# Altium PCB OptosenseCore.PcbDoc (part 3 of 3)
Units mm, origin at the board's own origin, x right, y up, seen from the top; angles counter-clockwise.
Board outline 65 x 56 mm, 4 copper layers (Top, Signal Layer 1, Power Layer 2, Bottom), stack 0.844 mm thick; 184 components, 119 nets, 728 pads, 633 vias.
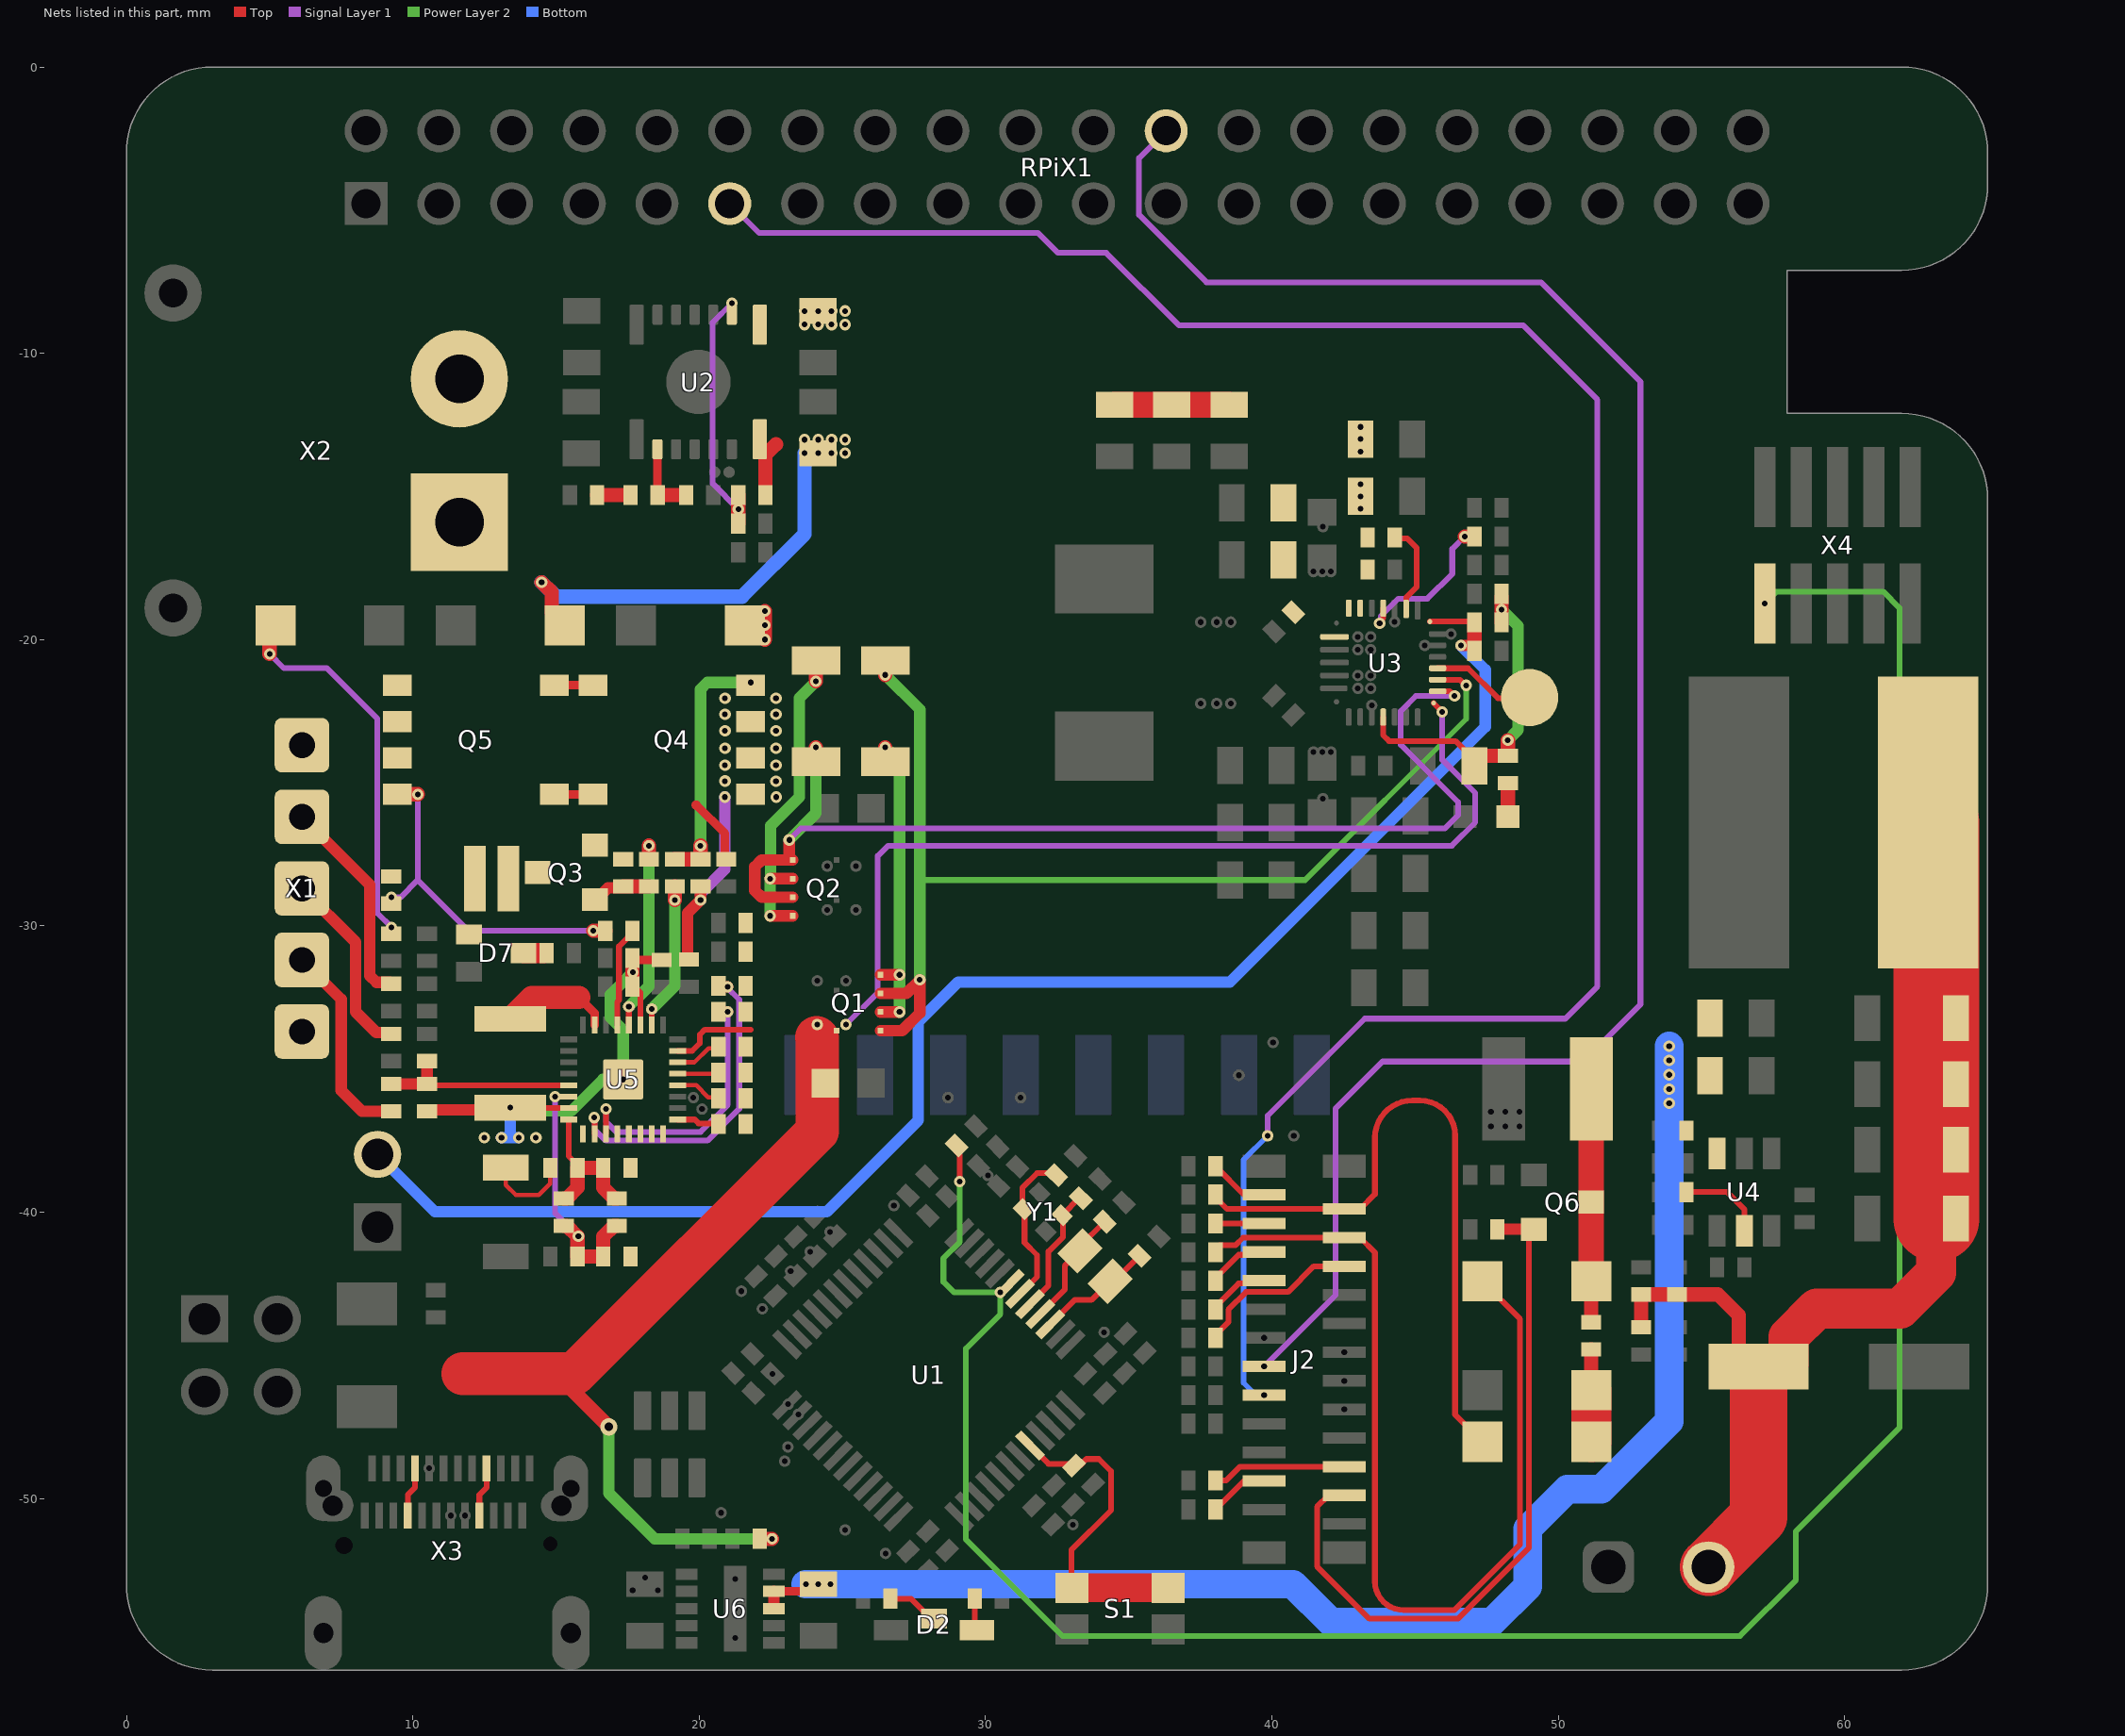
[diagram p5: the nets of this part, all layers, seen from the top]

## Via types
v1: diameter 0.4, hole 0.2, Top to Bottom, tented both sides, 616 vias
v2: diameter 0.5, hole 0.2, Top to Bottom, tented bottom, 11 vias
v3: diameter 4, hole 2.75, Top to Bottom, 4 vias
v4: diameter 0.4, hole 0.2, Top to Bottom, tented bottom, 1 vias
v5: diameter 0.6, hole 0.3, Top to Bottom, tented bottom, 1 vias

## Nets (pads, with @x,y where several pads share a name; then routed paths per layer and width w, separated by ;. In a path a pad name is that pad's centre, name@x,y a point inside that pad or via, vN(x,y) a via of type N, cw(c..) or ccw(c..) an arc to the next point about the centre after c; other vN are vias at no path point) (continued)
NetC62_1: C62.1 C64.2 R46.2 U5.5 | length 7
  Top w0.2: C64.2@10.5,-35.525 10.541,-35.566 U5.5@15.446,-35.566
  Top w0.4: R46.2@9.25,-35.525 C64.2@10.5,-35.525 C62.1@10.5,-34.725
NetC66_2: C66.2 U5.31 | length 3.9
  Top w0.3: 15.8,-32.5 16.346,-33.046 U5.31@16.346,-33.466
  Top w0.8: C66.2@13.4,-33.25 14.15,-32.5 15.8,-32.5
NetC67_1: C67.1 C68.2 C69.1 R53.2 U5.8 | length 5.4
  Top w0.2: U5.8@15.446,-36.766 15.446,-38.046 15.75,-38.35 R53.2@15.75,-38.45
  Top w0.5: C69.1@15.275,-39.525 15.375,-39.525 15.75,-39.15 R53.2@15.75,-38.45 C68.2@16.65,-38.45 16.65,-39.15 17.025,-39.525 C67.1@17.125,-39.525
NetC67_2: C67.2 C69.2 C70.1 R54.2 U5.6 | length 9.3
  Top w0.2: v1(14.966,-35.966) U5.6@15.446,-35.966
  Top w0.5: C69.2@15.275,-40.475 15.375,-40.475 15.75,-40.85 R54.2@15.75,-41.55 C70.1@16.65,-41.55 16.65,-40.85 17.025,-40.475 C67.2@17.125,-40.475
  Signal Layer 1 w0.2: v1(14.966,-35.966) 14.966,-40.027 v1(15.784,-40.845)
NetC71_1: C71.1 D11.A L3.2 Q6.C | length 8.3
  Top w0.5: C71.1@51.153,-43.847 D11.A@51.153,-42.422
  Top w0.9: D11.A@51.153,-42.422 L3.2@51.153,-35.5
NetC71_2: C71.2 D10.C D12.A | length 3.9
  Top w0.2: D12.A@50.675,-46.5 D12.A@51.153,-46.022
  Top w0.5: D12.A@51.153,-46.222 C71.2@51.153,-44.797
  Top w1.4: D10.C@51.153,-48.022 D12.A@51.153,-46.222
NetD2_1: D2.1 R12.2 | length 1.8
  Top w0.2: R12.2@26.675,-53.5 27.4,-53.5 28.1,-54.2 D2.1@28.2,-54.2
NetD2_3: D2.3 R13.2 | length 1.1
  Top w0.2: R13.2@29.625,-53.5 29.625,-54.525 D2.3@29.7,-54.6
NetD3_1: D3.1 Q1.2 Q1.4 | length 11.3
  Top w0.4: Q1.2@26.335,-33.01 v1(27,-33.01) ; Q1.4@26.335,-31.71 v1(27,-31.71)
  Top w0.5: D3.1@26.5,-24.265 v1(26.5,-23.765)
  Power Layer 2 w0.4: v1(26.5,-23.765) 27,-24.265 v1(27,-31.71) v1@27,-32.984
NetD3_2: D3.2 Q1.1 Q1.3 U3.11 | length 39.7
  Top w0.2: U3.11@45.788,-21.405 46.57,-21.405 46.814,-21.649 v1@46.836,-21.649
  Top w0.4: Q1.1@26.335,-33.66 27.093,-33.66 27.706,-33.047 v1(27.706,-31.888) 27.235,-32.36 Q1.3@26.335,-32.36
  Top w0.5: v1(26.5,-21.235) D3.2@26.5,-20.735
  Power Layer 2 w0.2: 27.706,-28.4 41.163,-28.4 46.787,-22.776 v1(46.787,-21.6)
  Power Layer 2 w0.4: v1(26.5,-21.235) 27.706,-22.441 27.706,-28.4 v1(27.706,-31.888)
NetD4_1: D4.1 Q2.2 Q2.4 | length 11.1
  Top w0.4: v1(22.484,-29.652) Q2.4@23.265,-29.652 ; v1(22.484,-28.352) Q2.2@23.265,-28.352
  Top w0.5: v1(24.079,-21.463) D4.1@24.079,-20.735
  Power Layer 2 w0.4: v1@22.484,-29.647 v1(22.484,-28.352) 22.5,-28.335 22.5,-26.5 23.5,-25.5 23.5,-22.042 v1(24.079,-21.463)
NetD4_2: D4.2 Q2.1 Q2.3 U3.10 | length 39.5
  Top w0.2: U3.10@45.788,-21.805 46.216,-21.805 v1(46.38,-21.969)
  Top w0.4: v1(23.147,-27) 23.147,-27.584 Q2.1@23.265,-27.702 22.18,-27.702 21.946,-27.936 21.946,-28.767 22.18,-29.002 Q2.3@23.265,-29.002
  Top w0.5: D4.2@24.079,-24.265 v1(24.079,-23.765)
  Signal Layer 1 w0.2: v1(23.147,-27) 23.547,-26.6 46.04,-26.6 46.5,-26.14 46.5,-25.674 44.5,-23.674 44.5,-22.5 45.031,-21.969 v1(46.38,-21.969)
  Power Layer 2 w0.4: v1(23.147,-27) 24.079,-26.068 v1(24.079,-23.765)
NetD5_A: D5.A R22.1 | length 1.2
  Top w0.5: R22.1@48.242,-25.011 48.245,-25.011 48.245,-26.184 D5.A@48.248,-26.187
NetD7_3: D7.3 R41.2 | length 0.7
  Top w0.7: D7.3@13.863,-30.951 R41.2@14.563,-30.951
NetQ3_B: Q3.B R33.2 R38.2 | length 2.1
  Top w0.4: Q3.B@16.362,-29.082 16.412,-29.082 16.819,-28.675 17.3,-28.675 R33.2@17.35,-28.625
  Top w0.5: R33.2@17.35,-28.625 R38.2@18.25,-28.625
NetQ3_C: Q3.C R32.2
NetQ3_E: Q3.E Q4.5 Q4.6 Q5.5 Q5.6 R33.1 R35.2 | length 5
  Top w0.3: Q5.5@14.95,-25.405 Q4.6@16.3,-25.405 ; Q5.6@14.95,-21.595 Q4.5@16.3,-21.595 ; 19.88,-25.78 19.905,-25.78 20.9,-26.775 R35.2@20.9,-27.6
NetQ4_4: Q4.4 R36.1 R40.2 | length 8.7
  Top w0.5: R40.2@19.15,-27.675 20.045,-27.675 20.048,-27.673 v1(20.048,-27.2)
  Power Layer 2 w0.4: v1(20.048,-27.2) 20.048,-21.737 20.284,-21.5 v1(21.8,-21.5)
NetQ5_4: Q5.4 R34.1 R39.2 | length 12.1
  Top w0.5: Q5.4@9.455,-25.405 v1(10.175,-25.405) ; v1(16.3,-30.175) R39.2@16.725,-30.175
  Signal Layer 1 w0.2: v1(9.256,-29.006) 9.57,-29.006 10.175,-28.4 ; v1@10.175,-25.426 10.175,-28.4 ; v1(16.3,-30.175) 11.95,-30.175 10.175,-28.4
NetR14_1: R14.1 R16.1 U2.2 | length 9.2
  Top w0.3: U2.2@21.144,-8.626 v1(21.144,-8.25)
  Top w0.5: R16.1@21.369,-15.951 21.369,-15.406 R14.1@21.369,-14.951
  Signal Layer 1 w0.2: v1(21.144,-8.25) 20.472,-8.922 20.472,-14.554 v1(21.369,-15.451)
NetR15_1: R15.1 R17.2 | length 1.1
  Top w0.5: R15.1@16.437,-14.951 R17.2@17.534,-14.951
NetR17_1: R17.1 R19.2 U2.9 | length 2.4
  Top w0.3: U2.9@18.544,-13.354 18.544,-14.944 R17.1@18.551,-14.951
  Top w0.5: R17.1@18.559,-14.951 R19.2@19.364,-14.951
NetR20_1: R20.1 U3.18 | length 3.2
  Top w0.2: R20.1@44.29,-16.438 44.315,-16.463 44.723,-16.463 45.06,-16.799 45.06,-18.161 44.688,-18.533 U3.18@44.688,-18.93
NetR21_2: R21.2 U3.20 | length 5.5
  Top w0.2: 43.888,-19.253 U3.20@43.888,-18.905
  Top w0.5: v1(46.736,-16.4) R21.2@47.074,-16.4
  Signal Layer 1 w0.2: v1(43.764,-19.431) 43.802,-19.393 43.802,-19.184 44.415,-18.572 45.434,-18.572 46.3,-17.706 46.3,-16.836 v1(46.736,-16.4)
NetR28_1: R28.1 U4.5 | length 3
  Top w0.2: R28.1@54.475,-39.3 55.9,-39.3 56.5,-39.9 U4.5@56.5,-40.65
NetR38_1: pad.3@18.25,-27.2 R38.1 U5.28 | length 7
  Top w0.2: U5.28@17.546,-33.466 v1(17.546,-32.817)
  Top w0.5: R38.1@18.25,-27.675 pad.3@18.25,-27.2
  Power Layer 2 w0.4: v1(17.546,-32.817) 18.25,-32.113 pad.3@18.25,-27.2
  Bottom w0.2: v1(17.546,-32.817) v1@17.558,-32.805
NetR39_1: R39.1 U5.29 | length 3.6
  Top w0.2: U5.29@17.146,-33.466 17.146,-32.651 17.2,-32.597 17.2,-30.717 17.492,-30.425 17.525,-30.425 17.75,-30.2 R39.1@17.75,-30.175
NetR40_1: pad.3@18.346,-32.907 pad.3@19.15,-29.1 R40.1 U5.26 | length 5.2
  Top w0.2: U5.26@18.346,-33.466 pad.3@18.346,-32.907
  Top w0.5: pad.3@19.15,-29.1 R40.1@19.15,-28.625
  Power Layer 2 w0.4: pad.3@18.346,-32.907 19.15,-32.103 pad.3@19.15,-29.1
NetR44_1: R44.1 X1.4 | length 7.4
  Top w0.4: X1.4@6.128,-26.192 8.5,-28.564 8.5,-31.741 8.734,-31.975 9.2,-31.975 R44.1@9.25,-32.025
NetR45_1: R45.1 X1.3 | length 6.7
  Top w0.4: X1.3@6.128,-28.692 8,-30.564 8,-33 8.725,-33.725 9.2,-33.725 R45.1@9.25,-33.775
NetR46_1: R46.1 X1.2 | length 7.2
  Top w0.4: X1.2@6.128,-31.192 7.5,-32.564 7.5,-35.75 8.224,-36.474 R46.1@9.1,-36.474 ; R46.1@9.101,-36.475 R46.1@9.25,-36.475
NetR47_2: R47.2 U5.11 | length 9.7
  Top w0.2: U5.11@16.746,-37.266 16.746,-36.395 v1(16.75,-36.391)
  Top w0.4: R47.2@20.675,-33 v1(21,-33)
  Signal Layer 1 w0.2: v1@16.75,-36.391 16.75,-36.846 17.104,-37.2 20.05,-37.2 21,-36.25 v1(21,-33)
NetR48_2: R48.2 U5.22 | length 1.6
  Top w0.152: U5.22@19.246,-34.766 19.834,-34.766 20.325,-34.275 20.525,-34.275 R48.2@20.625,-34.175
NetR49_2: R49.2 U5.21 | length 1.4
  Top w0.152: U5.21@19.246,-35.166 20.601,-35.166 R49.2@20.603,-35.167
NetR50_2: R50.2 U5.20 | length 1.7
  Top w0.152: U5.20@19.246,-35.566 19.898,-35.566 20.319,-35.987 20.501,-35.987 20.625,-36.111 R50.2@20.625,-36.2
NetR51_2: R51.2 U5.17 | length 1.4
  Top w0.2: U5.17@19.246,-36.766 19.846,-36.766 19.981,-36.9 R51.2@20.6,-36.9
NetTP1_1: TP1.1 U3.12 | length 3.8
  Top w0.2: U3.12@45.788,-21.005 46.851,-21.005 47.892,-22.046 48.646,-22.046 TP1.1@49,-22.4
NRST: C4.2 U1.7 X4.10 | length 88.1
  Top w0.2: C4.2@28.993,-37.674 28.993,-37.886 29.101,-37.994 v1(29.101,-38.927)
  Power Layer 2 w0.2: v1(29.101,-38.927) 29.101,-41.043 28.532,-41.612 28.532,-42.433 28.899,-42.8 v1(30.52,-42.8) 30.52,-43.562 29.318,-44.764 29.318,-51.432 32.686,-54.8 56.349,-54.8 58.3,-52.849 58.3,-51.149 61.916,-47.533 61.916,-18.891 61.35,-18.325 57.628,-18.325 v1(57.211,-18.741)
"OSC IN": C1.2 U1.5 Y1.3 | length 4.5
  Top w0.2: U1.5@31.56,-43.209 32.2,-42.569 32.2,-41.373 32.707,-40.866 32.707,-40.071 33.261,-39.517 C1.2@33.331,-39.517
OSC_OUT: C2.2 U1.6 Y1.1 | length 5.6
  Top w0.2: U1.6@31.206,-42.855 31.8,-42.262 31.8,-41.5 31.364,-41.064 31.364,-39.929 Y1.1@31.328,-39.894 31.293,-39.859 31.293,-39.144 31.801,-38.635 32.403,-38.635 C2.2@32.474,-38.706
"PC14-OSC32 IN": C5.2 U1.3 Y2.1 | length 4.2
  Top w0.2: U1.3@32.232,-43.951 33.114,-43.069 33.7,-43.069 Y2.1@34.355,-42.414 34.491,-42.414 C5.2@35.38,-41.525
PC15-OSC32_OUT: C6.2 U1.4 Y2.2 | length 4.2
  Top w0.2: U1.4@31.878,-43.598 32.769,-42.706 32.769,-41.878 Y2.2@33.294,-41.353 33.294,-41.198 C6.2@34.161,-40.331
PH3-BOOT0: R11.2 S1.1 S1.3 U1.44 | length 11.4
  Top w0.2: U1.44@31.525,-48.123 32.196,-48.795 R11.2@33.036,-48.795 ; S1.1@33.025,-53.122 33,-53.097 33,-51.8 34.385,-50.415 34.385,-49.05 33.957,-48.622 33.526,-48.622 33.301,-48.848 R11.2@33.089,-48.848
  Top w1: S1.1@33.025,-53.122 S1.3@36.375,-53.122
PowerStage: C49.1 C50.1 C51.1 C52.1 C53.1 C54.2 J_Interlock1.2 L2.2 R2.2 R27.2 | length 37.8
  Top w0.5: R2.2@52.9,-44.025 C54.2@52.9,-42.875 R27.2@54.15,-42.875 55.575,-42.875 56.3,-43.6 C53.1@56.3,-45
  Top w1: 63.2,-41.162 63.786,-40.577 63.79,-40.577 63.84,-40.527 63.84,-40.277 C52.1@63.89,-40.227
  Top w1.4: C53.1@57,-45.4 57.95,-45.4 58.05,-45.3 58.05,-44.35 59.028,-43.372 61.94,-43.372 63.2,-42.112 63.2,-41.162
  Top w2: J_Interlock1.2@55.25,-52.4 57,-50.65 C53.1@57,-45.7
  Top w3: 63.2,-40.227 63.2,-37.827 63.2,-35.527 63.2,-33.227 L2.2@63.2,-26.4
PREVGH: C76.2 D11.C J2.21 | length 33.9
  Top w0.2: C76.2@38.032,-41.4 38.032,-41.3 38.182,-41.15 38.739,-41.15 38.997,-40.892 43.08,-40.892 43.6,-41.412 43.6,-52.9 ccw(c44.6,-52.9) 44.6,-53.9 46.376,-53.9 48.666,-51.609 48.666,-43.735 D11.C@47.353,-42.422
PREVGL: C75.2 D10.A J2.23 | length 23.1
  Top w0.2: C75.2@38.032,-39.387 38.032,-39.487 38.437,-39.892 43.08,-39.892 43.6,-39.371 43.6,-37.404 cw(c44.904,-37.404) 44.904,-36.1 45.17,-36.1 cw(c45.17,-37.33) 46.4,-37.33 46.4,-47.069 47.142,-47.811 D10.A@47.211,-47.811
REGN_CHG: C40.2 R22.2 R23.2 R24.2 U3.5 | length 12.2
  Top w0.2: U3.5@43.888,-22.705 43.888,-23.339 44.094,-23.546 46.41,-23.546 46.723,-23.859 47.073,-23.859 C40.2@47.073,-24.409
  Top w0.5: C40.2@47.023,-24.061 R22.2@48.235,-24.061 ; R24.2@48.025,-19.4 v1(48.025,-18.95) R23.2@48.025,-18.5 ; R22.2@48.242,-24.061 R22.2@48.275,-24.061 ; R22.2@48.242,-24.061 v1(48.242,-23.521)
  Power Layer 2 w0.4: v1(48.025,-18.95) 48.6,-19.525 48.6,-22.4 48.6,-23.156 v1@48.235,-23.521
RES#: J2.10 pad.3@39.73,-46.392 pad.3@39.853,-37.333 RPiX1.11 | length 77.6
  Signal Layer 1 w0.2: RPiX1.11@21.07,-4.77 22.1,-5.8 31.836,-5.8 32.526,-6.49 34.217,-6.49 36.75,-9.023 48.774,-9.023 51.371,-11.62 51.371,-32.12 50.251,-33.24 43.246,-33.24 39.853,-36.633 pad.3@39.853,-37.333
  Bottom w0.2: pad.3@39.73,-46.392 39.442,-46.392 39.014,-45.964 39.014,-38.172 pad.3@39.853,-37.333
RESET: J2.3 Q6.E R56.2 | length 24.8
  Top w0.2: J2.3@42.53,-49.892 41.98,-49.892 41.58,-50.292 41.58,-52.374 43.406,-54.2 46.5,-54.2 48.971,-51.729 48.971,-40.829 Q6.E@49.2,-40.6
  Top w0.4: R56.2@47.95,-40.6 Q6.E@49.2,-40.6
SPI_Display_CS: J2.12 pad.3@39.73,-45.392 RPiX1.24 | length 67.2
  Signal Layer 1 w0.2: RPiX1.24@36.31,-2.23 35.36,-3.18 35.36,-5.164 37.719,-7.523 49.396,-7.523 52.871,-10.998 52.871,-32.741 50.872,-34.74 43.867,-34.74 42.23,-36.377 42.23,-42.892 pad.3@39.73,-45.392
TS1: R52.2 U5.10 | length 11.4
  Top w0.2: v1(16.337,-36.698) 16.346,-36.707 U5.10@16.346,-37.266
  Top w0.4: R52.2@20.675,-32.1 20.7,-32.125 v1(21,-32.125)
  Signal Layer 1 w0.2: v1(16.337,-36.698) 16.348,-36.708 16.348,-37.106 16.742,-37.5 20.291,-37.5 21.4,-36.391 21.4,-32.575 v1@20.975,-32.15
TS_CHG: P2.2 R24.1 R26.2 U3.16 | length 54.5
  Top w0.2: U3.16@45.519,-19.374 47.049,-19.374 R24.1@47.075,-19.4
  Top w0.4: v1(46.603,-20.205) 47.073,-20.205 47.075,-20.203 R26.2@47.081,-20.196
  Top w0.5: R26.2@47.075,-20.203 R24.1@47.075,-19.475
  Bottom w0.4: P2.2@8.77,-37.98 10.78,-39.99 24.455,-39.99 27.649,-36.795 27.649,-33.361 29.05,-31.96 38.54,-31.96 47.453,-23.047 47.453,-21.055 v1(46.603,-20.205)
VBAT: C35.2 C36.1 C37.1 D8.C Q4.1 Q4.2 Q4.3 R20.2 R36.2 R37.2 U3.22 U3.23 | length 7.4
  Top w0.4: R37.2@19.595,-31.137 19.595,-29.555 v1(20.049,-29.1) R36.2@20.05,-28.625
  Top w0.5: v1(22.3,-20) v1(22.3,-19.5) v1(22.3,-19)
  Signal Layer 1 w0.4: 20.049,-28.875 20.9,-28.024 v1(20.9,-25.5)
  other v1: 22.689,-25.501 20.904,-24.943 22.685,-24.944 20.904,-24.384 22.685,-24.385 20.904,-23.8 22.685,-23.801 20.904,-23.19 22.685,-23.192 20.904,-22.606 22.685,-22.607 20.904,-22.047 22.685,-22.049 43.1,-15.436 43.1,-15 43.1,-14.573 43.1,-13.436 43.1,-13 43.1,-12.573
VBUS: C23.2 pad.3@22.548,-51.41 Q1.9 Q1.9.1 Q1.9.2 R1.2 U3.9 X3.A04 X3.A09 X3.B04 X3.B09 | length 66.9
  Top w0.2: X3.B09@9.825,-50.6 9.825,-49.875 10.075,-49.625 X3.A04@10.075,-48.95 ; X3.B04@12.325,-50.6 12.325,-49.875 12.575,-49.625 X3.A09@12.575,-48.95 ; U3.9@45.65,-22.217 45.949,-22.516 v1(45.949,-22.53)
  Top w0.5: 14.997,-45.647 v5(16.85,-47.5) ; R1.2@22.116,-51.41 pad.3@22.548,-51.41
  Top w1.5: 11.753,-45.647 14.997,-45.647 15.653,-45.647 24.125,-37.175 24.125,-33.925 24.1,-33.9
  Signal Layer 1 w0.2: Q1.9.1@25.125,-33.448 26.239,-32.333 26.239,-27.561 26.6,-27.2 46.288,-27.2 47.1,-26.388 47.1,-25.358 45.949,-24.206 v1(45.949,-22.53)
  Power Layer 2 w0.4: v5(16.85,-47.5) 16.85,-49.819 18.441,-51.41 pad.3@22.548,-51.41
VCOM: C78.2 J2.24 | length 2.1
  Top w0.2: C78.2@38.032,-38.396 39.027,-39.392 J2.24@39.73,-39.392
VDD: C81.2 J2.18 | length 2.2
  Top w0.2: C81.2@38.032,-43.4 38.032,-43.3 38.841,-42.492 39.63,-42.492 J2.18@39.73,-42.392
VGH: C82.2 J2.5 | length 4.7
  Top w0.2: C82.2@38.032,-49.369 38.411,-49.369 38.888,-48.892 J2.5@42.53,-48.892
VGL: C83.2 J2.4 | length 2.1
  Top w0.2: C83.2@38.032,-50.385 39.026,-49.392 J2.4@39.73,-49.392
VPP: C77.2 J2.19 | length 5.8
  Top w0.2: C77.2@38.032,-44.39 38.032,-44.29 38.482,-43.84 38.482,-43.407 39.097,-42.792 40.563,-42.792 41.463,-41.892 J2.19@42.53,-41.892
VSH: C80.2 J2.20 | length 2.2
  Top w0.2: C80.2@38.032,-42.4 38.032,-42.3 38.84,-41.492 39.63,-41.492 J2.20@39.73,-41.392
VSL: C79.2 J2.22 | length 1.7
  Top w0.2: C79.2@38.032,-40.4 38.04,-40.392 J2.22@39.73,-40.392
VSS_Gauge: C55.2 C56.2 C57.1 C58.2 C59.2 C64.1 C66.1 C68.1 C70.2 NT2.2 R47.1 R48.1 R49.1 R50.1 R51.1 R52.1 U5.7 U5.9 U5.12 U5.13 U5.14 U5.15 U5.16 U5.23 U5.27 U5.33 | length 20.7
  Top w0.2: v1(13.4,-36.35) 13.416,-36.366 U5.7@15.446,-36.366 ; C59.2@17.711,-32.089 17.946,-32.324 U5.27@17.946,-33.466 ; U5.23@19.246,-34.366 19.761,-34.366 20.025,-34.102 20.025,-33.8 20.2,-33.625 21.8,-33.625
  Top w0.3: v1(17.681,-31.616) 17.678,-31.613 17.678,-31.128 17.737,-31.187 C57.1@18.689,-31.187
  Top w0.4: C64.1@10.5,-36.475 10.55,-36.425 13.325,-36.425 v1(13.4,-36.35)
  Top w0.5: C59.2@17.675,-32.125 C58.2@17.675,-31.125
  Power Layer 2 w0.4: v1(13.4,-36.35) 13.516,-36.466 15.537,-36.466 16.637,-35.366 v4(17.346,-35.366) 17.346,-33.646 16.9,-33.2 16.9,-32.398 v1(17.681,-31.616)
VSYS: C19.1 C20.1 C24.2 C25.1 C26.1 C27.1 C28.1 C29.1 C46.1 C47.1 C48.2 C65.2 D6.A pad.3@23.724,-52.997 pad.3@24.165,-52.997 pad.3@24.587,-52.997 R14.2 U2.1 U2.14 U3.25 U4.3 U6.3 U6.4 | length 71.7
  Top w0.3: U6.4@22.61,-53.247 23.915,-53.247 C65.2@24.165,-52.997 ; v1(24.155,-13.492) C20.1@24.355,-13.492
  Top w0.4: U2.1@22.119,-9.004 U2.1@22.119,-8.554 ; U6.3@22.61,-53.847 U6.4@22.61,-53.247
  Top w0.5: v1(14.5,-18) 14.85,-18.35 14.85,-19.05 D6.A@15.3,-19.5 ; R14.2@22.319,-14.951 22.319,-13.546 22.682,-13.183
  Top w0.9: C25.1@34.504,-11.8 C26.1@36.504,-11.8 C27.1@38.504,-11.8
  Bottom w0.5: v1(14.5,-18) 15,-18.5 21.5,-18.5 23.684,-16.316 v1(23.684,-13.492)
  Bottom w1: pad.3@23.724,-52.997 pad.3@24.165,-52.997 pad.3@24.587,-52.997 40.736,-52.997 42.066,-54.327 47.687,-54.327 48.935,-53.079 48.935,-51.059 50.314,-49.68 51.507,-49.68 53.875,-47.311 v1(53.875,-36.2) v1(53.875,-35.7) v1(53.875,-35.2) v1(53.875,-34.7) v1(53.875,-34.2)
  other v1: 24.626,-13.492 25.098,-13.492 23.684,-13.018 24.155,-13.018 24.626,-13.018 25.098,-13.018 23.683,-8.998 24.155,-8.998 24.626,-8.998 25.097,-8.998 23.683,-8.523 24.155,-8.523 24.626,-8.523 25.097,-8.523
XT_N: NT2.1 R53.1 R55.1 X1.1 X2.2 | length 4.1
  Top w0.15: R55.1@13.25,-38.45 13.25,-39.05 13.6,-39.4 14.4,-39.4 14.8,-39 R53.1@14.8,-38.45
  Bottom w0.4: v1(13.1,-37.4) v1(13.7,-37.4) ; 13.4,-37.36 NT2.1@13.4,-36.86
  other v1: 12.5,-37.4 14.3,-37.4
XT_P: D7.1 D9.A Q5.1 Q5.2 Q5.3 R32.1 R34.2 R42.1 X1.5 X2.1 | length 13.9
  Top w0.4: X1.5@6.128,-24.028 X1.5@6.128,-23.692
  Top w0.5: v1(5,-20.5) 5,-19.705 D9.A@5.205,-19.5
  Signal Layer 1 w0.2: v1(5,-20.5) 5.5,-21 7,-21 8.766,-22.766 8.766,-29.56 9.256,-30.051 v1(9.256,-30.056)
  Power Layer 2 w1: X1.5@6.128,-23.692 X1.5@6.392,-23.692
pads on no net: D1.5 D7.2 J2.1 J2.6 J2.7 J2.MP1 J2.MP2 J2.MP3 J2.MP4 RPiX1.1 RPiX1.3 RPiX1.5 RPiX1.7 RPiX1.12 RPiX1.13 RPiX1.15 RPiX1.16 RPiX1.17 RPiX1.27 RPiX1.28 RPiX1.29 RPiX1.31 RPiX1.32 RPiX1.33 RPiX1.35 RPiX1.36 RPiX1.37 RPiX1.38 RPiX1.40 U1.30 U1.40 U1.45 U1.46 U2.4 U2.5 U2.6 U2.13 U3.6 U3.7 U6.5 U6.8 U6.9 U6.10 X2. X3. X3.A02 X3.A03 X3.A08 X3.A10 X3.A11 X3.B02 X3.B03 X3.B08 X3.B10 X3.B11 X4.8
copper on no net:
  other v3: 3.5,-52.5 61.5,-52.5 3.5,-3.5 61.5,-3.5

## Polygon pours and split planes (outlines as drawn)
5V1 on Power Layer 2 "5V1_L03_P292" (solid, remove dead copper, pour order 292): 7.954,-0.661 11.156,-0.66 12.289,-1.793 12.289,-6.105 14.267,-8.084 18.059,-8.084 18.059,-9.525 16.5,-9.525 15.4,-10.42 15.4,-11.642 16.6,-12.471 18.059,-12.471 18.059,-13.837 13.926,-13.837 13.166,-13.075 13.166,-10.417 10.808,-10.417 6.815,-6.424 6.815,-1.8
GND on Power Layer 2 "GND_L03_P305" (solid, pour order 305): 15.113,-12.471 15.113,-18 21.869,-18 21.869,-13.919 21.869,-12.471 25.146,-12.471 25.146,-9.525 21.869,-9.525 21.869,-6 15.113,-6 15.113,-9.525
XT_N on Signal Layer 1 "Signal Layer 1-XT_N" (solid, remove dead copper, pour order 307): 0.002,-32.939 6.652,-39.589 13.552,-39.589 14.502,-38.639 14.502,-35.877 8.502,-29.878 8.502,-13.924 9.887,-12.539 11.63,-12.539 11.63,-9.139 0.002,-9.139
External_Voltage_Source on Signal Layer 1 "EXTERNAL_VOLTAGE_SOURCE_L02_P287" (solid, pour order 287): 21.615,-26.67 25.959,-26.67 25.959,-37.694 18.237,-45.415 10.312,-45.415 8.173,-47.555 0,-47.555 0,-45 6.664,-45 9.398,-42.266 17.069,-42.266 21.615,-37.719
5V1 on Signal Layer 1 "5V1_L02_P319" (solid, remove dead copper, pour order 319): 7.954,-0.661 11.156,-0.66 12.289,-1.793 12.289,-6.105 14.267,-8.084 18.059,-8.084 18.059,-9.525 16.5,-9.525 15.4,-10.42 15.4,-11.642 16.6,-12.471 18.059,-12.471 18.059,-13.837 13.926,-13.837 13.166,-13.075 13.166,-10.417 10.808,-10.417 6.815,-6.424 6.815,-1.8
VBAT on Signal Layer 1 "VBAT_L02_P288" (solid, pour order 288): 20.447,-25.781 24.054,-25.781 24.054,-22.174 30.072,-16.156 43.55,-16.156 43.55,-12.351 42.649,-12.351 41.731,-13.269 27.015,-13.269 20.447,-19.837
GND on Signal Layer 1 "GND_L02_P283" (solid, pour order 283): 57.1,-31.6 61.3,-31.6 61.3,-42.3 57.1,-42.3 57.1,-36
GND on Top "tgh" (solid, remove dead copper, pour order 317): 9.2,-56 9.2,-56.038 18.825,-55.976 18.825,-56 53.5,-56 53.5,-26.695 46.228,-26.695 46.025,-26.492 46.025,-24.181 45.593,-23.749 43.586,-23.749 43.586,-25.186 43.942,-25.542 43.942,-31.826 42.868,-32.9 28.9,-32.9 26.799,-35.001 25.968,-35.001 25.968,-38.732 24.35,-40.35 24.706,-40.706 18.825,-46.632 18.825,-48.5 9.5,-48.5 9.5,-46.2 11.3,-44.4 14.3,-44.4 14.3,-41.452 0,-41.452 0,-56
XT_P on Top "Top-XT_P" (solid, remove dead copper, pour order 315): 0,-14.091 0,-20.828 7.572,-28.4 10.172,-28.4 11.5,-29.728 11.5,-30.65 12.55,-30.65 12.55,-26.701 10.8,-25.014 10.8,-17.699 12.888,-17.699 12.888,-14.091
GND on Top "Top-GND 1" (solid, remove dead copper, pour order 312): 61.449,-35.944 65.278,-35.944 65.278,-2.311 65.329,-2.261 63.246,-0.178 1.778,-0.178 1.6,0 -0.025,-1.626 -0.025,-7.44 12.04,-7.44 14.196,-9.596 14.203,-21.139 26.238,-21.139 26.238,-28.909 30.35,-28.902 31.27,-29.896 39.338,-29.896 39.338,-23.527 41.726,-21.139 43.758,-21.139 43.758,-22.225 45.35,-22.225 45.35,-19.718 41.282,-19.718 41.282,-13.743 42.602,-12.423 42.606,-13.271 44.05,-13.268 44.054,-15.999 45.059,-16.941 45.059,-18.1 46.664,-18.1 46.693,-15.4 48.175,-15.4 48.169,-17.75 50.05,-17.75 56.003,-23.703 56.003,-36.092 57.1,-36.092 57.1,-42.4 61.3,-42.4 61.3,-36.092
GND on Top "GND_L01_P311" (solid, pour order 311): 42.603,-17.986 42.603,-11.938 48.133,-11.938 49.149,-12.954 49.149,-15.494 49.149,-15.113 48.768,-15.494 46.711,-15.494 46.711,-16.307 44.679,-16.307 44.691,-17.967
VSS_Gauge on Top "VSS_Gauge" (solid, remove dead copper, pour order 286): 17.349,-41.55 17.349,-39.24 15.588,-39.24 15.588,-36.8 14.2,-36.8 14.2,-36.2 16.053,-36.2 16.053,-37.247 20.903,-37.247 21.375,-36.775 21.375,-29.55 21.9,-29.55 21.9,-37.282 17.632,-41.55
VBUS on Top "VBUS_L01_P276" (solid, pour order 276): 9.825,-51.15 12.575,-51.15 12.575,-44.9 11.4,-44.9 9.825,-46.475
External_Voltage_Source on Top "EXTERNAL_VOLTAGE_SOURCE_L01_P316" (solid, remove dead copper, pour order 316): 24.875,-25.9 24.875,-28.552 23.88,-28.552 23.88,-26.444 24.424,-25.9
VBAT on Top "VBAT_L01_P310" (solid, pour order 310): 20.447,-25.781 22.978,-25.781 22.981,-25.784 22.981,-21.991 22.784,-21.793 20.625,-21.793 20.447,-21.971
5V1 on Top "5V1_L01_P309" (solid, pour order 309): 18.059,-9.525 15.113,-9.525 15.113,-8.077 18.059,-8.077
5V1 on Top "5V1_L01_P308" (solid, pour order 308): 18.059,-12.471 15.113,-12.471 15.113,-13.945 18.059,-13.945
VSYS on Top "VSYS_L01_P303" (solid, remove dead copper, pour order 303): 22.235,-53.047 22.975,-53.047 23.475,-52.547 24.815,-52.547 24.815,-53.447 23.617,-53.447 23.016,-54.047 22.235,-54.047
3V3 on Top "3V3_L01_P297" (solid, remove dead copper, pour order 297): 17.36,-52.447 18.985,-52.447 19.085,-52.347 20.035,-52.347 20.035,-53.547 17.36,-53.547
VBAT on Top "VBAT_L01_P296" (solid, pour order 296): 42.589,-19.152 43.184,-19.152 43.188,-18.527 43.739,-17.976 43.739,-16.256 43.942,-16.002 43.942,-13.268 42.587,-13.268 42.587,-19.127
NetC41_2 on Top "NETC41_2_L01_P295" (solid, pour order 295): 42.364,-21.605 41.285,-21.605 39.446,-23.444 39.446,-29.044 41.021,-29.044 41.021,-22.751 41.963,-21.809
NetC17_2 on Top "NETC17_2_L01_P294" (solid, remove dead copper, pour order 294): 35.869,-24.927 32.426,-24.927 32.426,-22.513 35.869,-22.52 37.004,-21.385 38.882,-21.385 38.882,-22.957
NetC18_2 on Top "NETC18_2_L01_P291" (solid, remove dead copper, pour order 291): 35.869,-16.678 32.426,-16.678 32.426,-19.092 35.869,-19.085 37.004,-20.22 38.882,-20.22 38.882,-18.648
CHARGER_VIN on Top "Top-NetC40_1" (solid, remove dead copper, pour order 289): 43.5,-25.364 43.5,-23.3 42.905,-22.705 42.596,-22.705 42.596,-25.146 42.596,-29.213 41.692,-30.099 31.545,-30.099 30.347,-28.902 23.88,-28.902 23.88,-29.982 22.905,-30.957 22.901,-32.475 25.72,-32.475 25.72,-31.363 27.757,-31.363 29.206,-32.813 42.955,-32.813 43.942,-31.826 43.942,-25.806
XT_N on Top "XT_N_L01_P284" (solid, remove dead copper, pour order 284): 14.63,-37.1 14.63,-37.49 14,-38.121 14,-38.6 12.5,-38.6 12.5,-37.9 12,-37.4 12,-37.1
NetQ3_C on Top "NetQ23_C" (solid, remove dead copper, pour order 281): 12.75,-29.5 14.25,-29.5 15,-28.75 15,-27.5 14.5,-27 12.75,-27
NetQ3_E on Top "NetQ23_E" (solid, remove dead copper, pour order 279): 10.92,-21.22 20.33,-21.22 20.33,-25.78 18.75,-25.75 17.7,-26.8 17.7,-27.925 16.175,-27.925 14,-25.75 10.92,-25.78
VSYS on Top "Top-VSYS" (solid, remove dead copper, pour order 278): 54.831,-39.1 55.838,-39.1 55.836,-32 54.5,-32 53.9,-31.4 53.9,-11.36 50.617,-8.077 22.125,-8.077 21.875,-8.3 21.875,-9.525 25.146,-9.525 25.146,-12.471 21.875,-12.471 21.875,-13.665 22.16,-13.95 28.45,-13.95 29.776,-12.624 39.322,-12.624 39.903,-13.206 39.903,-18.675 41.158,-19.929 41.234,-20.005 41.834,-20.005 41.834,-19.909 40.791,-18.505 40.791,-13.665 43.382,-11.074 48.682,-11.074 50.232,-12.624 50.232,-30.632 53.074,-33.474 53.374,-33.774 53.374,-36.062 54.3,-36.987 54.3,-37.5 54.831,-37.5
GND on Bottom "GND_L04_P302" (solid, remove dead copper, pour order 302): 0,-53 0,-3 cw(c3,-3) 3,0 61.996,0 cw(c61.996,-3.004) 65,-3.004 65,-3 65,-4 cw(c61.996,-4) 61.996,-7.004 62,-7 58,-7 58,-12.1 62,-12.1 cw(c62,-15.104) 65.004,-15.104 65,-15 65,-52.996 cw(c61.996,-52.996) 61.996,-56 3,-56 cw(c3,-53)
3V3 on Bottom "Bottom-3V3" (solid, remove dead copper, pour order 282): 17,-56 45,-56 45,-37.998 50.952,-37.998 50.952,-35.814 43.79,-35.814 27.864,-35.814 17,-46.678
VSYS on Bottom "VSYS_L04_P301" (solid, remove dead copper, pour order 301): 23.401,-12.736 25.38,-12.736 25.38,-13.775 23.401,-13.775
VSYS on Bottom "VSYS_L04_P300" (solid, remove dead copper, pour order 300): 23.401,-8.241 25.38,-8.241 25.38,-9.28 23.401,-9.28
5V1 on Bottom "5V1_L04_P299" (solid, remove dead copper, pour order 299): 15.133,-12.736 17.112,-12.736 17.112,-13.775 15.133,-13.775
5V1 on Bottom "5V1_L04_P293" (solid, remove dead copper, pour order 293): 15.146,-8.241 17.125,-8.241 17.125,-9.28 15.146,-9.28

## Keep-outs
Keep-Out Layer:
  region: 65,0 65,-7 58,-7 58,0
  lines w0.4: 44,-52.598 44.038,-52.792 44.114,-52.974 44.223,-53.137 44.363,-53.277 44.526,-53.386 44.708,-53.462 44.902,-53.5 45.098,-53.5 45.292,-53.462 45.474,-53.386 45.637,-53.277 45.777,-53.137 45.886,-52.974 45.962,-52.792 46,-52.598 46,-52.5 46,-37.5 46,-37.402 45.962,-37.208 45.886,-37.026 45.777,-36.863 45.637,-36.723 45.474,-36.614 45.292,-36.538 45.098,-36.5 44.902,-36.5 44.708,-36.538 44.526,-36.614 44.363,-36.723 44.223,-36.863 44.114,-37.026 44.038,-37.208 44,-37.402 44,-37.5 44,-52.5 44,-52.598

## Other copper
Top:
  pour cut-out: 32.438,-25.044 32.438,-21.392 38.872,-21.392 38.882,-20.22 32.438,-20.222 32.438,-16.575 31,-16.575 31,-25.035
Bottom:
  pour cut-out: 30.996,-17.414 37.018,-17.414 38.868,-19.265 38.868,-22.361 37.014,-24.215 30.996,-24.215
  pour cut-out: 15.3,-33.4 19.4,-33.4 19.4,-37.4 15.3,-37.4

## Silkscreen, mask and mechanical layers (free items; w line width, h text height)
Top Overlay:
  text "+" at 57.7,-55.869 h4
Bottom Overlay:
  text "______" at 38.215,-37.365 h1.27 r180
  text "SMBUS Clock" at 23.445,-42 h1.27 r90
  text "SMBUS Data" at 25.985,-42 h1.27 r90
  text "I2C SCL" at 28.525,-42 h1.27 r90
  text "I2C SDA" at 31.065,-42 h1.27 r90
  text "GND" at 33.605,-42 h1.27 r90
  text "5.1V" at 36.145,-42 h1.27 r90
  text "Power Switch" at 40.755,-42 h1.27 r90
Mechanical 12:
  the board outline again, w0.4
